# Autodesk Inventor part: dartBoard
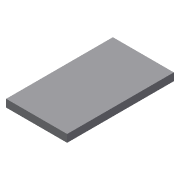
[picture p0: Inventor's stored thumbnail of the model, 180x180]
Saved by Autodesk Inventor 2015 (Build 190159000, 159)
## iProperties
Created: 2016-07
Part Number: dartBoard
Material: EIFS, Exterior Insulation
Document SubType Name: Modeling
Designer: user
Density: 0.023 g/cm^3
Appearance: Gray
Author: user
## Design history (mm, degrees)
sketch "Sketch1"
  geometry: L1 (0, 0)-(-50.8, 0); L2 (-50.8, 0)-(-50.8, -88.9); L3 (-50.8, -88.9)-(0, -88.9); L4 (0, -88.9)-(0, 0)
  constraints: 8 end point, 2 parallel, 1 horizontal, 1 perpendicular
  dimensions: "d0" = 50.8 distance of L3.end L2.end; "d1" = 88.9 distance of L2.end L1.end
extrude "Extrusion1" new body sketch "Sketch1" distance "d2" = 6.35; taper "d3" = 0 deg
body "Solid1"
